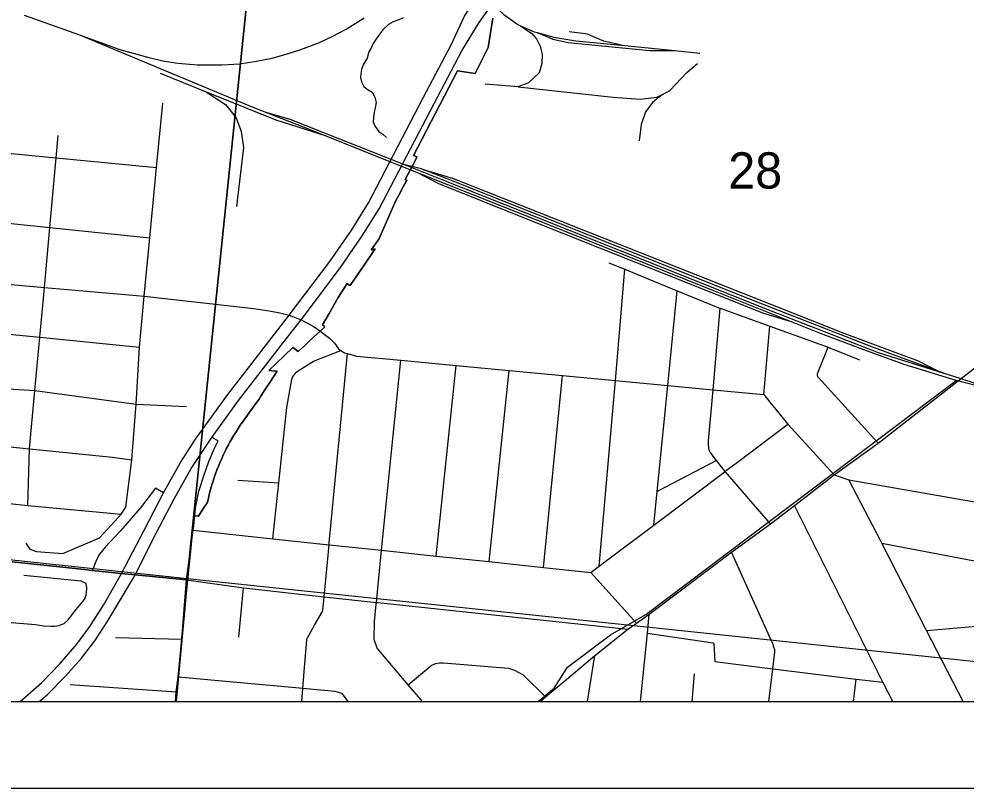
# Model space of a CAD drawing. Extents: x 0 to 34, y -3.9 to 26.2.
# Drawn here: x 3.386 to 4.481, y 14 to 14.888 of the extents above; entities that cross this region are included whole.
import ezdxf

# ---------------------------------------------------------------- set-up
doc = ezdxf.new("R2010")
doc.units = 0
for name, color, linetype in [('GM_X_City_Street', 7, 'Continuous'), ('GM_X_County_Road', 7, 'Continuous'), ('GM_X_Interchange_Ramps', 7, 'Continuous'), ('GM_X_Interstate_Route', 7, 'Continuous'), ('GM_X_Minor_River', 7, 'Continuous'), ('GM_X_Rail_Line', 7, 'Continuous'), ('GM_X_Section', 7, 'Continuous'), ('GM_X_Section_Text', 7, 'Continuous'), ('GM_X_State_Route', 7, 'Continuous'), ('GM_X_State_Shield', 7, 'Continuous'), ('SH_Data', 7, 'Continuous')]:
    doc.layers.add(name, color=color, linetype=linetype)

msp = doc.modelspace()

# ---------------------------------------------------------------- linework, layer by layer
at = {"layer": 'GM_X_City_Street'}
for p, q in [((4.2471, 14.4543), (4.2541, 14.5332)), ((3.8684, 14.2678), (3.8917, 14.4879)), ((3.9297, 14.2614), (3.9529, 14.4821)), ((3.9926, 14.2547), (4.0146, 14.4763)), ((4.2152, 14.3753), (4.2748, 14.4202)), ((4.1925, 14.3781), (4.1238, 14.3423)), ((3.5801, 14.2403), (3.5877, 14.2976)), ((4.0999, 14.1902), (4.0472, 14.249)), ((3.6405, 14.1742), (3.6458, 14.2311)), ((4.435, 14.1821), (4.5692, 14.1937)), ((3.4981, 14.1738), (3.5748, 14.1719)), ((4.0434, 14.1), (4.0519, 14.1532)), ((4.1642, 14.1), (4.1671, 14.1318)), ((3.4458, 14.1194), (3.5682, 14.1111)), ((4.3505, 14.1), (4.3539, 14.1258))]:
    msp.add_line(p, q, dxfattribs=at)
for points in [[(3.5044, 14.3162), (3.5101, 14.3242), (3.5169, 14.379), (3.522, 14.4434), (3.5256, 14.5089), (3.5313, 14.5679), (3.5377, 14.6354), (3.5455, 14.7167), (3.5526, 14.7907)], [(3.0114, 14.763), (3.0216, 14.7662), (3.0379, 14.7655), (3.2011, 14.7498), (3.3134, 14.739), (3.322, 14.7382), (3.4296, 14.7278), (3.5455, 14.7167)], [(3.3967, 14.3264), (3.3988, 14.3916), (3.405, 14.4592), (3.4106, 14.5205), (3.4147, 14.5652), (3.4159, 14.578), (3.4222, 14.6474), (3.4296, 14.7278), (3.4319, 14.7536)], [(3.112, 14.6763), (3.1941, 14.6711), (3.3142, 14.6586), (3.4222, 14.6474), (3.5377, 14.6354)], [(4.0569, 14.2563), (4.0755, 14.4705), (4.0866, 14.599)], [(4.0679, 14.6066), (4.0866, 14.599), (4.1143, 14.5876), (4.147, 14.5743), (4.1952, 14.5545), (4.1966, 14.554), (4.2541, 14.5332), (4.3212, 14.5089), (4.3223, 14.5085), (4.3576, 14.4943)], [(4.1199, 14.3037), (4.1238, 14.3423), (4.136, 14.4648), (4.147, 14.5743)], [(4.2546, 14.305), (4.2022, 14.3656), (4.1925, 14.3781), (4.1852, 14.3877), (4.184, 14.3902), (4.1834, 14.393), (4.1831, 14.3969), (4.1832, 14.401), (4.1884, 14.4598), (4.1966, 14.554)], [(3.2529, 14.5362), (3.4106, 14.5205), (3.5256, 14.5089)], [(3.6799, 14.2877), (3.6867, 14.3524), (3.6958, 14.4394), (3.7017, 14.4721), (3.7026, 14.4745), (3.7044, 14.4771), (3.7072, 14.4802), (3.7092, 14.4819), (3.7102, 14.4827), (3.7268, 14.4929), (3.7584, 14.5053)], [(3.7159, 14.1347), (3.7166, 14.1437), (3.719, 14.1707), (3.7192, 14.1721), (3.7199, 14.1736), (3.728, 14.1882), (3.7371, 14.2037), (3.7373, 14.2043), (3.7375, 14.205), (3.739, 14.2209), (3.7448, 14.2809), (3.745, 14.2831), (3.766, 14.5016)], [(4.3793, 14.3982), (4.3097, 14.4744), (4.3093, 14.475), (4.309, 14.4762), (4.3089, 14.4772), (4.3091, 14.4784), (4.311, 14.4834), (4.3212, 14.5089)], [(3.7984, 14.2043), (3.7992, 14.2122), (3.7994, 14.2143), (3.8055, 14.2745), (3.8278, 14.494)], [(3.2868, 14.4664), (3.405, 14.4592), (3.522, 14.4434), (3.5799, 14.4407)], [(3.1838, 14.4136), (3.3202, 14.3997), (3.3988, 14.3916), (3.4945, 14.3819), (3.5169, 14.379)], [(4.0648, 14.2622), (4.1199, 14.3037), (4.2022, 14.3656), (4.2039, 14.3669), (4.2152, 14.3753)], [(3.176, 14.3519), (3.3541, 14.3309), (3.3967, 14.3264), (3.5044, 14.3162)], [(3.6395, 14.3555), (3.6631, 14.354), (3.6867, 14.3524)], [(4.4772, 14.1), (4.435, 14.1821), (4.3834, 14.2827), (4.3818, 14.2858), (4.3453, 14.3557)], [(4.3962, 14.1), (4.3845, 14.1221), (4.2823, 14.3262)], [(3.3945, 14.2829), (3.399, 14.2758), (3.4067, 14.2732), (3.4371, 14.271), (3.4794, 14.2889), (3.4976, 14.3085), (3.5044, 14.3162)], [(3.5877, 14.2976), (3.6799, 14.2877), (3.7448, 14.2809), (3.8055, 14.2745), (3.8684, 14.2678), (3.9297, 14.2614), (3.9926, 14.2547), (4.0472, 14.249), (4.0543, 14.2543), (4.0569, 14.2563), (4.0648, 14.2622)], [(4.3834, 14.2827), (4.4987, 14.261), (4.5291, 14.2553), (4.6263, 14.237)], [(4.253, 14.1), (4.2575, 14.1377), (4.2598, 14.1568), (4.2598, 14.1582), (4.2596, 14.1597), (4.2588, 14.1627), (4.2574, 14.1668), (4.2556, 14.1707), (4.2098, 14.2724)], [(3.3733, 14.1915), (3.4058, 14.1888), (3.4149, 14.1874), (3.4232, 14.1868), (3.4281, 14.1871), (3.4327, 14.1877), (3.4388, 14.1899), (3.4431, 14.194), (3.4521, 14.2059), (3.4622, 14.2178), (3.4642, 14.2227), (3.4647, 14.2257), (3.4648, 14.2311), (3.4642, 14.236), (3.4582, 14.2388), (3.392, 14.2454)], [(3.8528, 14.1), (3.836, 14.119), (3.8005, 14.1615), (3.797, 14.1715), (3.7972, 14.1924), (3.7984, 14.2043)], [(4.1125, 14.179), (4.1884, 14.1675), (4.1892, 14.167), (4.1906, 14.146), (4.2575, 14.1377), (4.3539, 14.1258), (4.3845, 14.1221)], [(3.836, 14.119), (3.8626, 14.1416), (3.8676, 14.1437), (3.8725, 14.1447), (3.8771, 14.1446), (3.9519, 14.1383), (3.9591, 14.136), (3.969, 14.1309), (3.9948, 14.1054)], [(3.7669, 14.1), (3.7636, 14.104), (3.7599, 14.109), (3.7517, 14.1115), (3.7144, 14.1149), (3.5703, 14.1279)], [(3.7133, 14.1), (3.7144, 14.1149), (3.7159, 14.1347)]]:
    msp.add_lwpolyline(points, dxfattribs=at)
at = {"layer": 'GM_X_County_Road'}
for p, q in [((3.3786, 14.2612), (3.4405, 14.2545)), ((3.5406, 14.2443), (3.5801, 14.2403))]:
    msp.add_line(p, q, dxfattribs=at)
for points in [[(3.1866, 14.6063), (3.308, 14.5875), (3.4159, 14.578), (3.5313, 14.5679), (3.658, 14.5536), (3.673, 14.5514), (3.6779, 14.5505)], [(3.6779, 14.5505), (3.6877, 14.5486), (3.6987, 14.5459), (3.7124, 14.5407), (3.7263, 14.5334), (3.7353, 14.5271)], [(3.7353, 14.5271), (3.7361, 14.5265), (3.7452, 14.5194), (3.7509, 14.5135), (3.7555, 14.5073), (3.7584, 14.5053)], [(4.3284, 14.3617), (4.3793, 14.3982), (4.5342, 14.5192)], [(3.7584, 14.5053), (3.7625, 14.5025), (3.766, 14.5016), (3.7764, 14.4988), (3.8278, 14.494), (3.8917, 14.4879), (3.9529, 14.4821), (4.0146, 14.4763), (4.0755, 14.4705), (4.136, 14.4648), (4.1884, 14.4598), (4.2471, 14.4543), (4.2541, 14.4457), (4.261, 14.4372)], [(4.261, 14.4372), (4.2748, 14.4202), (4.3284, 14.3617)], [(4.0195, 14.1259), (4.0519, 14.1532), (4.09, 14.1833), (4.0999, 14.1902), (4.1145, 14.2007), (4.2098, 14.2724), (4.2546, 14.305), (4.2823, 14.3262), (4.3284, 14.3617)], [(4.3284, 14.3617), (4.3453, 14.3557), (4.5105, 14.327), (4.6114, 14.3326), (4.7448, 14.3401), (4.795, 14.3429), (4.8053, 14.3436), (4.8422, 14.3461), (4.8505, 14.3466), (4.8905, 14.3523), (4.9069, 14.3546), (4.9398, 14.3614), (4.9576, 14.365), (4.9641, 14.3664), (5.1075, 14.3635), (5.1135, 14.3614), (5.1215, 14.3586), (5.1453, 14.3489), (5.1981, 14.3273), (5.2207, 14.318), (5.364, 14.2594)], [(3.4405, 14.2545), (3.4622, 14.2522), (3.471, 14.2512)], [(3.471, 14.2512), (3.5049, 14.2477), (3.5208, 14.2463), (3.5406, 14.2443)], [(3.5801, 14.2403), (3.6458, 14.2311), (3.739, 14.2209), (3.7994, 14.2143), (3.8013, 14.2141), (4.09, 14.1833)], [(4.1044, 14.1), (4.1125, 14.179), (4.1145, 14.2007)], [(3.9886, 14.1), (3.9948, 14.1054), (4.0195, 14.1259)]]:
    msp.add_lwpolyline(points, dxfattribs=at)
at = {"layer": 'GM_X_Interchange_Ramps'}
for points in [[(2.1, 14.1), (3.5682, 14.1), (3.5803, 14.2327), (3.5845, 14.2735), (3.5887, 14.3145), (3.5938, 14.3141), (3.599, 14.3221), (3.6038, 14.3293), (3.6043, 14.3302), (3.6053, 14.3345), (3.606, 14.3375), (3.6063, 14.3388), (3.6074, 14.343), (3.6079, 14.3448), (3.6086, 14.3473), (3.6099, 14.3515), (3.61, 14.352), (3.6112, 14.3557), (3.6124, 14.3593), (3.6126, 14.3599), (3.6141, 14.364), (3.6152, 14.367), (3.6156, 14.3682), (3.6173, 14.3723), (3.6183, 14.3747), (3.6189, 14.3764), (3.6207, 14.3804), (3.6216, 14.3823), (3.6225, 14.3844), (3.6244, 14.3884), (3.6252, 14.3899), (3.6264, 14.3923), (3.6285, 14.3962), (3.629, 14.3972), (3.6306, 14.4001), (3.6327, 14.4039), (3.633, 14.4044), (3.6344, 14.4068), (3.635, 14.4077), (3.6373, 14.4115), (3.6396, 14.4151), (3.6397, 14.4152), (3.6421, 14.4189), (3.6433, 14.4206), (3.6446, 14.4225), (3.6455, 14.4238), (3.6496, 14.4294), (3.6529, 14.434), (3.6562, 14.4385), (3.6612, 14.4454), (3.6639, 14.4491), (3.666, 14.4524), (3.6707, 14.4597), (3.6746, 14.4656), (3.675, 14.4663), (3.6798, 14.4737), (3.6847, 14.4812), (3.6786, 14.4818), (3.6785, 14.4818), (3.6753, 14.4822), (3.6928, 14.4989), (3.703, 14.5086), (3.7055, 14.5067), (3.709, 14.5039), (3.7139, 14.5085), (3.7147, 14.5092), (3.7214, 14.5155), (3.7312, 14.5246), (3.7383, 14.531), (3.74, 14.5327), (3.7393, 14.5333), (3.737, 14.5349), (3.7447, 14.5481), (3.7554, 14.5665), (3.7658, 14.5825), (3.7677, 14.5812), (3.769, 14.5804), (3.794, 14.6169), (3.7966, 14.6206), (3.7981, 14.6228), (3.7934, 14.6216), (3.8021, 14.6336), (3.8137, 14.6598), (3.822, 14.6783), (3.8264, 14.6865), (3.8282, 14.6899), (3.8346, 14.7018), (3.8326, 14.7026), (3.8445, 14.725), (3.8461, 14.729), (3.8424, 14.7304), (3.8881, 14.8185), (3.8932, 14.8283), (3.9134, 14.8249), (3.9284, 14.8552), (3.934, 14.889)], [(3.934, 14.889), (3.9284, 14.8552), (3.9134, 14.8249), (3.8932, 14.8283), (3.8881, 14.8185), (3.8424, 14.7304), (3.8461, 14.729), (3.8445, 14.725), (3.8326, 14.7026), (3.8346, 14.7018), (3.8282, 14.6899), (3.8264, 14.6865), (3.822, 14.6783), (3.8137, 14.6598), (3.8021, 14.6336), (3.7934, 14.6216), (3.7981, 14.6228), (3.7966, 14.6206), (3.794, 14.6169), (3.769, 14.5804), (3.7677, 14.5812), (3.7658, 14.5825), (3.7554, 14.5665), (3.7447, 14.5481), (3.737, 14.5349), (3.7393, 14.5333), (3.74, 14.5327), (3.7383, 14.531), (3.7312, 14.5246), (3.7214, 14.5155), (3.7147, 14.5092), (3.7139, 14.5085), (3.709, 14.5039), (3.7055, 14.5067), (3.703, 14.5086), (3.6928, 14.4989), (3.6753, 14.4822), (3.6785, 14.4818), (3.6786, 14.4818), (3.6847, 14.4812), (3.6798, 14.4737), (3.675, 14.4663), (3.6746, 14.4656), (3.6707, 14.4597), (3.666, 14.4524), (3.6639, 14.4491), (3.6612, 14.4454), (3.6562, 14.4385), (3.6529, 14.434), (3.6496, 14.4294), (3.6455, 14.4238), (3.6446, 14.4225), (3.6433, 14.4206), (3.6421, 14.4189), (3.6396, 14.4151), (3.6373, 14.4115), (3.635, 14.4077), (3.6344, 14.4068), (3.633, 14.4044), (3.6327, 14.4039), (3.6306, 14.4001), (3.629, 14.3972), (3.6285, 14.3962), (3.6264, 14.3923), (3.6252, 14.3899), (3.6244, 14.3884), (3.6225, 14.3844), (3.6216, 14.3823), (3.6207, 14.3804), (3.6189, 14.3764), (3.6183, 14.3747), (3.6173, 14.3723), (3.6156, 14.3682), (3.6152, 14.367), (3.6141, 14.364), (3.6126, 14.3599), (3.6112, 14.3557), (3.61, 14.352), (3.6099, 14.3515), (3.6086, 14.3473), (3.6079, 14.3448), (3.6074, 14.343), (3.6063, 14.3388), (3.606, 14.3375), (3.6053, 14.3345), (3.6043, 14.3302), (3.6038, 14.3293), (3.599, 14.3221), (3.5938, 14.3141), (3.5887, 14.3145), (3.5845, 14.2735), (3.5803, 14.2327), (3.5682, 14.1), (7.2913, 14.1)], [(3.5896, 14.3149), (3.5904, 14.3233), (3.5944, 14.3428), (3.6, 14.3604), (3.6059, 14.3769), (3.6123, 14.3923), (3.6166, 14.4011), (3.6094, 14.4048)], [(3.5535, 14.3409), (3.5444, 14.3462), (3.5292, 14.3265), (3.5264, 14.3232)], [(3.5264, 14.3232), (3.5034, 14.2966), (3.4866, 14.2784), (3.4794, 14.27), (3.4756, 14.2627), (3.473, 14.2554), (3.471, 14.2512)], [(3.5877, 14.2976), (3.5885, 14.3029), (3.5896, 14.3149)]]:
    msp.add_lwpolyline(points, dxfattribs=at)
at = {"layer": 'GM_X_Interstate_Route'}
for points in [[(3.388, 14.1), (3.4125, 14.1216), (3.4341, 14.1437), (3.4532, 14.1663), (3.4683, 14.1867), (3.484, 14.211), (3.5049, 14.2477), (3.5312, 14.2978), (3.5535, 14.3409), (3.5733, 14.3758), (3.5905, 14.4028), (3.6279, 14.4543), (3.679, 14.5208), (3.6987, 14.5459), (3.7456, 14.6081), (3.7709, 14.6445), (3.7902, 14.6759), (3.854, 14.7976), (3.8858, 14.8581), (3.9014, 14.8914), (3.917, 14.916), (3.931, 14.9385), (3.9442, 14.9571), (3.9609, 14.9774)], [(3.4099, 14.1), (3.4191, 14.1078), (3.4402, 14.1291), (3.4586, 14.1501), (3.4742, 14.1699), (3.4891, 14.1929), (3.5176, 14.2408), (3.5208, 14.2463), (3.5446, 14.2936), (3.5658, 14.3339), (3.5856, 14.3688), (3.6094, 14.4048), (3.6402, 14.4473), (3.6913, 14.5138), (3.7124, 14.5407), (3.758, 14.6011), (3.7832, 14.6375), (3.8025, 14.6688), (3.8663, 14.7906), (3.8981, 14.8511), (3.9174, 14.8827), (3.9317, 14.9031), (3.9347, 14.9069)], [(2.5468, 14.1), (8.9, 14.1)]]:
    msp.add_lwpolyline(points, dxfattribs=at)
at = {"layer": 'GM_X_Minor_River'}
msp.add_lwpolyline([(3.8303, 14.8893), (3.8253, 14.8872), (3.8187, 14.8848), (3.8133, 14.8816), (3.8069, 14.8754), (3.8033, 14.871), (3.7997, 14.8655), (3.7957, 14.8599), (3.7936, 14.8543), (3.7907, 14.8499), (3.7889, 14.8427), (3.7841, 14.8349), (3.7823, 14.8297), (3.7814, 14.8252), (3.7812, 14.8206), (3.7821, 14.8153), (3.785, 14.8102), (3.7901, 14.8062), (3.7946, 14.8037), (3.7978, 14.7979), (3.7991, 14.7914), (3.7981, 14.7853), (3.7967, 14.7801), (3.7961, 14.7744), (3.7959, 14.7694), (3.798, 14.764), (3.8023, 14.7582), (3.8067, 14.7549), (3.8112, 14.7513)], dxfattribs=at)
at = {"layer": 'GM_X_Rail_Line'}
for p, q in [((3.3927, 14.8923), (3.4565, 14.8699)), ((4.0827, 14.8578), (4.1444, 14.8518)), ((4.1444, 14.8518), (4.1732, 14.8487)), ((3.6032, 14.8034), (3.5501, 14.8251)), ((3.9631, 14.8095), (3.9251, 14.8126)), ((4.4551, 14.4789), (4.4493, 14.481))]:
    msp.add_line(p, q, dxfattribs=at)
for points in [[(3.9376, 15.0219), (3.9239, 15.0049), (3.9189, 14.9891), (3.915, 14.9727), (3.9142, 14.9554), (3.9179, 14.9369), (3.9272, 14.9159), (3.9356, 14.9032), (3.9465, 14.8933), (3.9627, 14.8816), (3.9658, 14.8802)], [(3.4565, 14.8699), (3.503, 14.8527), (3.5367, 14.8434), (3.5548, 14.8395), (3.5701, 14.8371), (3.5928, 14.8351), (3.6212, 14.8351), (3.6415, 14.8364), (3.6611, 14.8393), (3.6789, 14.8429), (3.6962, 14.8476), (3.7123, 14.8527), (3.7337, 14.861), (3.7482, 14.8678), (3.7645, 14.8764), (3.7855, 14.8895)], [(3.9658, 14.8802), (3.979, 14.8713), (3.9843, 14.8652), (3.9888, 14.8565), (3.9911, 14.8471), (3.9907, 14.8368), (3.9874, 14.8257), (3.9751, 14.8142), (3.9631, 14.8095)], [(3.9658, 14.8802), (3.9818, 14.8732), (3.9853, 14.8723)], [(3.9853, 14.8723), (4.0032, 14.8646), (4.0209, 14.8609), (4.115, 14.8516), (4.1444, 14.8518)], [(3.9853, 14.8723), (4.0044, 14.867), (4.0299, 14.8629), (4.0827, 14.8578)], [(4.0827, 14.8578), (4.0622, 14.8623), (4.0503, 14.8674), (4.0435, 14.8703), (4.0379, 14.8713), (4.0223, 14.873)], [(3.4565, 14.8699), (3.6567, 14.7863), (3.7237, 14.7599), (3.8371, 14.7147), (3.9711, 14.6613), (4.1871, 14.5754), (4.3121, 14.5254), (4.3591, 14.5075), (4.4089, 14.4895), (4.4679, 14.4714), (4.493, 14.4649), (4.5245, 14.458), (4.5504, 14.4533), (4.5793, 14.4489), (4.6136, 14.4445), (4.6414, 14.442), (4.6736, 14.4392), (4.7148, 14.4381), (4.7717, 14.4384), (4.881, 14.4458), (4.9881, 14.4546), (5.1478, 14.4677), (5.2664, 14.4774), (5.3957, 14.4877)], [(4.1298, 14.801), (4.1384, 14.8054), (4.1582, 14.8261), (4.1703, 14.8368)], [(3.9631, 14.8095), (4.0729, 14.7976), (4.1041, 14.7955), (4.1236, 14.7978), (4.1298, 14.801)], [(3.7417, 14.7527), (3.6837, 14.7713), (3.6088, 14.8012), (3.6032, 14.8034)], [(3.6032, 14.8034), (3.6251, 14.7891), (3.6373, 14.7739), (3.6433, 14.7582), (3.6458, 14.7398), (3.6379, 14.6714)], [(4.1298, 14.801), (4.1187, 14.7918), (4.1105, 14.7809), (4.1055, 14.7661), (4.1031, 14.7472)], [(3.6717, 14.7804), (3.6996, 14.7725), (3.8325, 14.7196)], [(3.8536, 14.7142), (3.8513, 14.7151), (3.8325, 14.7196)], [(3.8325, 14.7196), (3.873, 14.7035), (3.9721, 14.664), (4.1882, 14.5781), (4.2485, 14.5539), (4.3791, 14.5029), (4.4551, 14.4789)], [(3.847, 14.7108), (3.8705, 14.6983), (3.97, 14.6586), (4.186, 14.5727), (4.2466, 14.5485), (4.2788, 14.5387)], [(4.4493, 14.481), (4.3737, 14.5086), (4.2425, 14.5597), (3.8814, 14.7033), (3.8536, 14.7142)], [(3.8536, 14.7142), (3.8873, 14.7041), (4.3393, 14.5251), (4.4252, 14.4933), (4.4493, 14.481)], [(4.4551, 14.4789), (4.4735, 14.4731), (4.5088, 14.4614)], [(3.9862, 14.1), (4.0048, 14.1155), (4.0203, 14.1394), (4.0701, 14.1769), (4.1108, 14.2002), (4.4691, 14.4706)]]:
    msp.add_lwpolyline(points, dxfattribs=at)
at = {"layer": 'GM_X_Section'}
for points in [[(2.6632, 15.3458), (3.6849, 15.247), (3.5807, 14.2417), (2.569, 14.3494)], [(3.6849, 15.247), (4.6963, 15.1472), (4.5981, 14.1346), (3.5807, 14.2417)]]:
    msp.add_lwpolyline(points, close=True, dxfattribs=at)
at = {"layer": 'GM_X_State_Route'}
for p, q in [((3.4405, 14.2545), (3.3786, 14.2612)), ((3.5801, 14.2403), (3.5406, 14.2443))]:
    msp.add_line(p, q, dxfattribs=at)
for points in [[(3.471, 14.2512), (3.4622, 14.2522), (3.4405, 14.2545)], [(3.5406, 14.2443), (3.5208, 14.2463), (3.5049, 14.2477), (3.471, 14.2512)], [(3.5673, 14.1), (3.5682, 14.1111), (3.5703, 14.1279), (3.5748, 14.1719), (3.5801, 14.2403)]]:
    msp.add_lwpolyline(points, dxfattribs=at)
at = {"layer": 'GM_X_State_Shield'}
for points in [[(2.5457, 14.1), (3.5681, 14.1), (3.5807, 14.2417), (2.569, 14.3494)], [(3.5681, 14.1), (4.5948, 14.1), (4.5981, 14.1346), (3.5807, 14.2417)]]:
    msp.add_lwpolyline(points, close=True, dxfattribs=at)
at = {"layer": 'SH_Data'}
msp.add_line((2, 14), (9, 14), dxfattribs=at)

# ---------------------------------------------------------------- texts
at = {"layer": 'GM_X_Section_Text'}
msp.add_text('28', height=0.04186, rotation=0, dxfattribs=at).set_placement((4.206, 14.6922))

doc.saveas('drawing.dxf')
